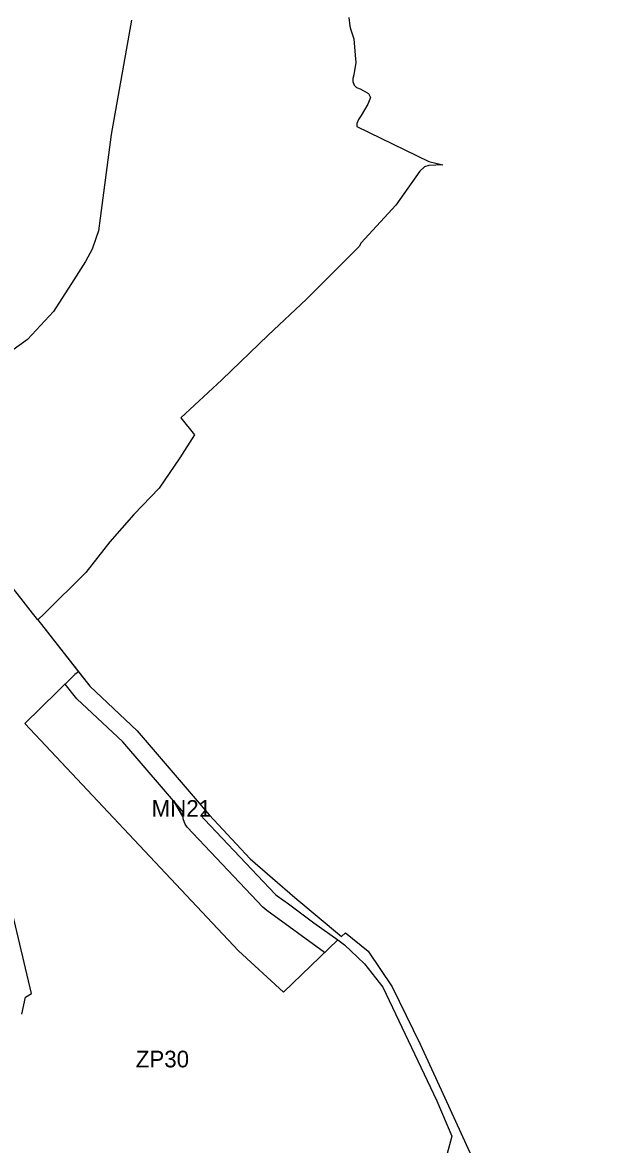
# Model space of a CAD drawing. Extents: x 7428080 to 7432143, y 5545880 to 5549217.
# Drawn here: x 7430925.4 to 7431120.9, y 5547441.7 to 5547815.6 of the extents above; entities that cross this region are included whole.
import ezdxf

# ---------------------------------------------------------------- set-up
doc = ezdxf.new("R2010")
doc.units = 0
for name, color, linetype in [('CZ_L_granica obszaru objętego planem', 7, 'Continuous'), ('CZ_L_linie rozgraniczające tereny o różnym przeznaczeniu oraz różnych warunkach ich zabudowy i zagospodarowania', 7, 'Continuous'), ('CZ_L_maksymalne nieprzekraczalne linie zabudowy', 7, 'Continuous'), ('CZ_L_opisy_linie rozgraniczające tereny o różnym przeznaczeniu oraz różnych warunkach ich zabudowy i zagospodarowania', 7, 'Continuous')]:
    doc.layers.add(name, color=color, linetype=linetype)

msp = doc.modelspace()

# ---------------------------------------------------------------- linework, layer by layer
at = {"layer": 'CZ_L_granica obszaru objętego planem'}
for p, q in [((7431034.05, 5547817.27), (7431034.37, 5547814.35)), ((7431034.37, 5547814.35), (7431034.78, 5547813.23)), ((7431034.78, 5547813.23), (7431035.77, 5547810.18)), ((7431035.77, 5547810.18), (7431036.14, 5547804.73)), ((7431036.14, 5547804.73), (7431036.39, 5547802.31)), ((7431036.39, 5547802.31), (7431035.73, 5547798.16)), ((7431035.73, 5547798.16), (7431035.41, 5547797.01)), ((7431035.41, 5547797.01), (7431035.45, 5547795.98)), ((7431035.45, 5547795.98), (7431035.81, 5547794.76)), ((7431035.81, 5547794.76), (7431036.61, 5547793.97)), ((7431036.61, 5547793.97), (7431037.87, 5547793.56)), ((7431037.87, 5547793.56), (7431040.6, 5547791.96)), ((7431041.28, 5547790.64), (7431040.39, 5547788.4)), ((7431040.6, 5547791.96), (7431041.28, 5547790.64)), ((7431040.39, 5547788.4), (7431038.16, 5547784.69)), ((7431037.28, 5547783.28), (7431036.77, 5547781.96)), ((7431038.16, 5547784.69), (7431037.28, 5547783.28)), ((7431036.77, 5547781.96), (7431036.76, 5547780.93)), ((7431036.76, 5547780.93), (7431060.72, 5547769.29)), ((7431059.3, 5547767.48), (7431057.7, 5547766.13)), ((7431060.72, 5547767.99), (7431059.3, 5547767.48)), ((7431060.72, 5547769.29), (7431065.36, 5547768.18)), ((7431065.36, 5547768.18), (7431060.72, 5547767.99)), ((7431057.7, 5547766.13), (7431049.68, 5547754.71)), ((7431049.68, 5547754.71), (7431038.12, 5547742.2)), ((7431038.12, 5547742.2), (7431037.55, 5547740.94)), ((7431037.55, 5547740.94), (7431020, 5547723.46)), ((7431020, 5547723.46), (7431007.21, 5547711.49)), ((7431007.21, 5547711.49), (7430991.77, 5547696.57)), ((7430991.77, 5547696.57), (7430978.07, 5547683.9)), ((7430978.07, 5547683.9), (7430982.66, 5547678.27)), ((7430982.66, 5547678.27), (7430977.75, 5547670.56)), ((7430977.75, 5547670.56), (7430970.93, 5547660.45)), ((7430970.93, 5547660.45), (7430962.5, 5547651.73)), ((7430962.5, 5547651.73), (7430954.5, 5547642.62)), ((7430954.5, 5547642.62), (7430946.48, 5547632.39)), ((7430946.48, 5547632.39), (7430932.7, 5547618.74)), ((7430932.7, 5547618.74), (7430930.48, 5547616.55)), ((7430930.48, 5547616.55), (7430947.83, 5547594.45)), ((7430947.83, 5547594.45), (7430963.56, 5547579.62)), ((7430963.56, 5547579.62), (7430987.53, 5547551.64)), ((7430987.53, 5547551.64), (7431001.23, 5547536.94)), ((7431001.23, 5547536.94), (7431016.1, 5547524.03)), ((7431016.1, 5547524.03), (7431031.6, 5547511.12)), ((7431031.6, 5547511.12), (7431032.93, 5547512.33)), ((7431032.93, 5547512.33), (7431040.53, 5547506.15)), ((7431040.53, 5547506.15), (7431048.48, 5547494.34)), ((7431048.48, 5547494.34), (7431057.8, 5547475.24)), ((7431057.8, 5547475.24), (7431066, 5547457.29)), ((7431066, 5547457.29), (7431074.9, 5547437.84))]:
    msp.add_line(p, q, dxfattribs=at)
at = {"layer": 'CZ_L_linie rozgraniczające tereny o różnym przeznaczeniu oraz różnych warunkach ich zabudowy i zagospodarowania'}
for p, q in [((7430961.7, 5547816.41), (7430954.88, 5547778.35)), ((7430954.88, 5547778.35), (7430951.21, 5547750.42)), ((7430951.21, 5547750.42), (7430950.73, 5547746.23)), ((7430950.73, 5547746.23), (7430949.83, 5547743.68)), ((7430949.83, 5547743.68), (7430948.57, 5547740.13)), ((7430948.57, 5547740.13), (7430946.39, 5547735.99)), ((7430946.39, 5547735.99), (7430942.53, 5547729.83)), ((7430942.53, 5547729.83), (7430935.77, 5547719.35)), ((7430935.77, 5547719.35), (7430927.02, 5547710)), ((7430927.02, 5547710), (7430922.34, 5547706.55)), ((7430925.59, 5547622.81), (7430919.13, 5547631.07)), ((7430928.7, 5547618.83), (7430925.59, 5547622.81)), ((7430930.48, 5547616.55), (7430928.7, 5547618.83)), ((7430930.48, 5547616.55), (7430944.01, 5547599.31)), ((7430944.01, 5547599.31), (7430942.84, 5547598.33)), ((7430942.37, 5547597.95), (7430926.16, 5547582)), ((7430942.84, 5547598.33), (7430942.37, 5547597.95)), ((7430926.16, 5547582), (7430997.27, 5547506.25)), ((7430928.41, 5547492.11), (7430922.07, 5547518.83)), ((7431012.34, 5547492.54), (7431030.41, 5547509.91)), ((7431030.41, 5547509.91), (7431032.57, 5547508.35)), ((7430997.27, 5547506.25), (7431012.34, 5547492.54)), ((7431032.57, 5547508.35), (7431036.98, 5547504.18)), ((7431036.98, 5547504.18), (7431039.29, 5547501.97)), ((7431039.29, 5547501.97), (7431045.43, 5547494.21)), ((7430925.17, 5547485.2), (7430926.44, 5547490.87)), ((7430926.44, 5547490.87), (7430928.41, 5547492.11)), ((7431045.43, 5547494.21), (7431063.36, 5547456.3)), ((7431063.36, 5547456.3), (7431068.4, 5547444.49)), ((7431068.4, 5547444.49), (7431066.66, 5547438.33))]:
    msp.add_line(p, q, dxfattribs=at)
for points in [[(7431034.05, 5547817.27), (7431034.37, 5547814.35), (7431034.78, 5547813.23), (7431035.77, 5547810.18), (7431036.14, 5547804.73), (7431036.39, 5547802.31), (7431035.73, 5547798.16), (7431035.41, 5547797.01), (7431035.45, 5547795.98), (7431035.81, 5547794.76), (7431036.61, 5547793.97), (7431037.87, 5547793.56), (7431040.6, 5547791.96), (7431041.28, 5547790.64), (7431040.39, 5547788.4), (7431038.16, 5547784.69), (7431037.28, 5547783.28), (7431036.77, 5547781.96), (7431036.76, 5547780.93), (7431060.72, 5547769.29), (7431065.36, 5547768.18), (7431060.72, 5547767.99), (7431059.3, 5547767.48), (7431057.7, 5547766.13), (7431049.68, 5547754.71), (7431038.12, 5547742.2), (7431037.55, 5547740.94), (7431020, 5547723.46), (7431007.21, 5547711.49), (7430991.77, 5547696.57), (7430978.07, 5547683.9), (7430982.66, 5547678.27), (7430977.75, 5547670.56), (7430970.93, 5547660.45), (7430962.5, 5547651.73), (7430954.5, 5547642.62), (7430946.48, 5547632.39), (7430932.7, 5547618.74), (7430930.48, 5547616.55)], [(7430944.01, 5547599.31), (7430947.83, 5547594.45), (7430963.56, 5547579.62), (7430986.2, 5547553.19)], [(7430986.2, 5547553.19), (7430984.79, 5547551.36), (7430986.03, 5547550.06), (7431009.56, 5547525.19), (7431009.69, 5547525.1), (7431009.8, 5547524.95), (7431010.25, 5547524.58), (7431013.92, 5547521.92), (7431018.42, 5547518.65), (7431018.41, 5547518.61), (7431022.41, 5547515.68), (7431030.41, 5547509.91)], [(7430986.2, 5547553.19), (7430987.53, 5547551.64), (7431001.23, 5547536.94), (7431016.1, 5547524.03), (7431031.6, 5547511.12), (7431032.93, 5547512.33), (7431040.53, 5547506.15), (7431048.48, 5547494.34), (7431057.8, 5547475.24), (7431066, 5547457.29), (7431074.9, 5547437.84), (7431078.67, 5547432.53), (7431081.21, 5547429.06), (7431084.68, 5547423.88), (7431087.93, 5547419.9), (7431097.2, 5547410.15), (7431104.64, 5547403.36), (7431110.55, 5547397.75), (7431116.54, 5547389.77), (7431120.88, 5547382.89)], [(7430986.21, 5547553.19), (7430986.2, 5547553.19)]]:
    msp.add_lwpolyline(points, dxfattribs=at)
at = {"layer": 'CZ_L_maksymalne nieprzekraczalne linie zabudowy'}
for points in [[(7430979.12, 5547552.24), (7430958.77, 5547575.89), (7430943.49, 5547590.31), (7430939.62, 5547595.19)], [(7431025.97, 5547505.72), (7431006.72, 5547519.73), (7431005.42, 5547520.85), (7430980.2, 5547547.51), (7430979.51, 5547548.51), (7430978.97, 5547549.93), (7430978.8, 5547551.13), (7430978.87, 5547552.31)]]:
    msp.add_lwpolyline(points, dxfattribs=at)

# ---------------------------------------------------------------- texts
at = {"layer": 'CZ_L_opisy_linie rozgraniczające tereny o różnym przeznaczeniu oraz różnych warunkach ich zabudowy i zagospodarowania'}
for s, p in [('MN21', (7430968.39, 5547550.96)), ('ZP30', (7430963.12, 5547467.47))]:
    msp.add_text(s, height=5.549, dxfattribs=at).set_placement(p)

doc.saveas('drawing.dxf')
